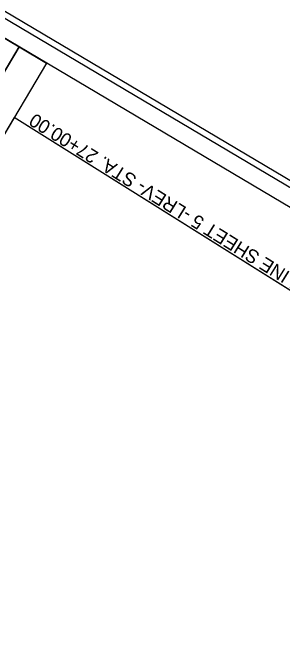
# Model space of a CAD drawing. Extents: x 2137081 to 2142019, y 404041 to 411238.
# Drawn here: x 2141211.9 to 2141410.8, y 410498.7 to 410963.6 of the extents above; entities that cross this region are included whole.
import ezdxf

# ---------------------------------------------------------------- set-up
doc = ezdxf.new("R2010")
doc.units = 0
for name, color, linetype in [('Prop Dimension', 7, 'Continuous'), ('Prop Dimension Text', 7, 'Continuous'), ('Sheet Clip Boundary CELL', 7, 'Continuous'), ('Sheet Plan And Profile CELL', 7, 'Continuous'), ('Sheet Plot Border Inside CELL', 7, 'Continuous'), ('Sheet Plot Border Outside CELL', 7, 'Continuous'), ('Sheet Sticker Exception Certification CELL', 7, 'Continuous')]:
    doc.layers.add(name, color=color, linetype=linetype)

msp = doc.modelspace()

# ---------------------------------------------------------------- linework, layer by layer
at = {"layer": 'Prop Dimension'}
msp.add_line((2141513.05, 410697.97), (2141213, 410886.12), dxfattribs=at)
at = {"layer": 'Sheet Clip Boundary CELL'}
msp.add_lwpolyline([(2140795, 409444.32), (2141473.2, 410586.96), (2141453.94, 410598.39), (2141513.05, 410697.97), (2141213, 410886.12), (2141134.78, 410754.33), (2141040.49, 410810.3), (2140938.2, 410637.97), (2140883.25, 410670.58), (2140322.04, 409725.04)], close=True, dxfattribs=at)
at = {"layer": 'Sheet Plan And Profile CELL'}
for points in [[(2141087.64, 411014.95), (2140322.04, 409725.04), (2141224.97, 409189.12), (2141990.57, 410479.02)], [(2141068.89, 410909.79), (2141119.93, 410995.78), (2141216.67, 410938.36), (2141165.63, 410852.37)]]:
    msp.add_lwpolyline(points, close=True, dxfattribs=at)
at = {"layer": 'Sheet Plot Border Inside CELL'}
msp.add_lwpolyline([(2141148.77, 409055.84), (2141999.1, 410488.49), (2141091.87, 411026.97), (2140241.54, 409594.32)], close=True, dxfattribs=at)
at = {"layer": 'Sheet Plot Border Outside CELL'}
msp.add_lwpolyline([(2141159.33, 409034.46), (2142018.6, 410482.16), (2141076.97, 411041.05), (2140217.7, 409593.35)], close=True, dxfattribs=at)
at = {"layer": 'Sheet Sticker Exception Certification CELL'}
for p, q in [((2141114.57, 410766.33), (2141216.67, 410938.35)), ((2141216.68, 410938.34), (2141236.89, 410926.35)), ((2141236.88, 410926.35), (2141134.78, 410754.33))]:
    msp.add_line(p, q, dxfattribs=at)

# ---------------------------------------------------------------- texts
at = {"layer": 'Prop Dimension Text'}
msp.add_text('MATCHLINE SHEET 5 -LREV- STA. 27+00.00', height=10, rotation=148.0236, dxfattribs=at).set_placement((2141463.7, 410742.75))

doc.saveas('drawing.dxf')
